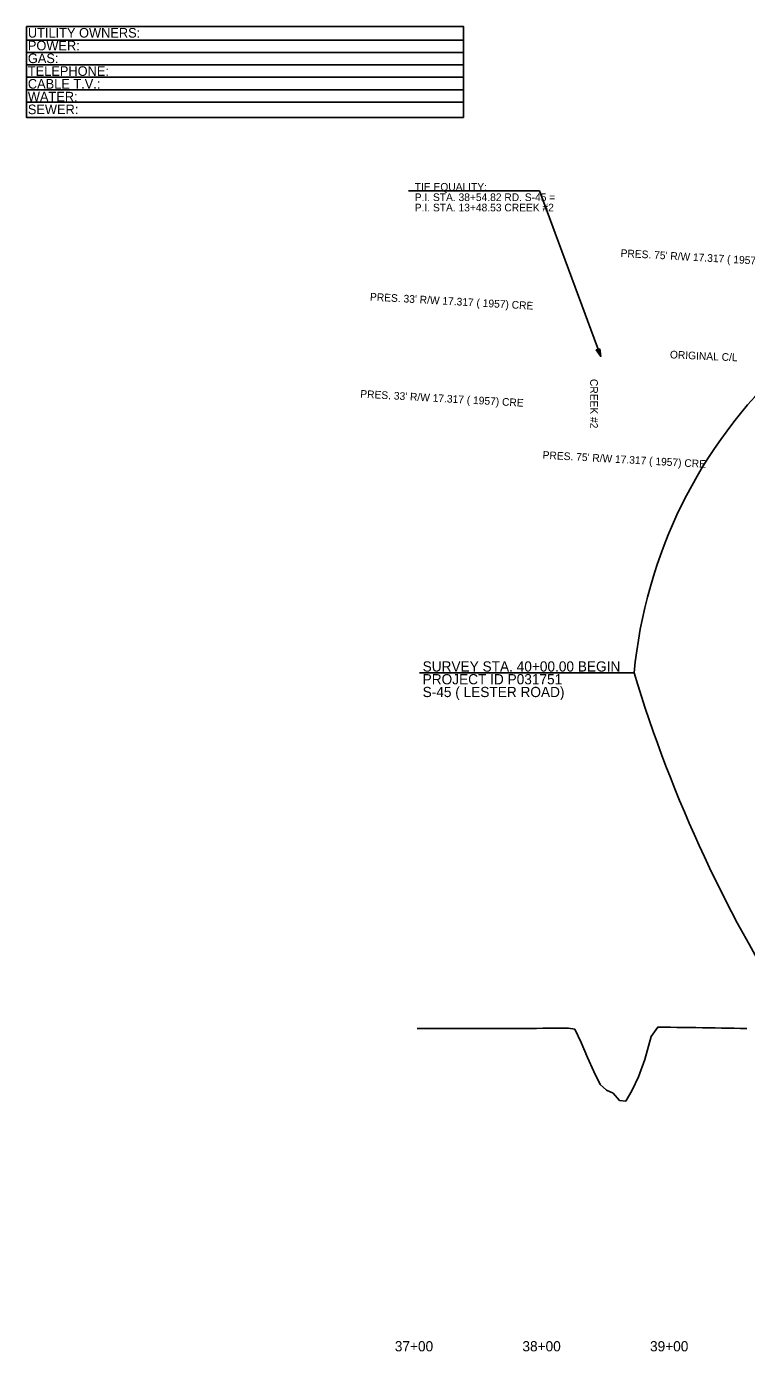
# Model space of a CAD drawing. Extents: x -3336 to 3318, y -3606 to 6276.
# Drawn here: x 119 to 683, y -509 to 529 of the extents above; entities that cross this region are included whole.
import ezdxf

# ---------------------------------------------------------------- set-up
doc = ezdxf.new("R2010")
doc.units = 0
for name, color, linetype in [('RD_DDB_Profile_EX', 7, 'Continuous'), ('RD_DDB_StaTX', 7, 'Continuous'), ('RD_EX_RW_TX', 7, 'Continuous'), ('RD_HC_Data', 7, 'Continuous'), ('RD_PD_Final_TX', 7, 'Continuous'), ('RD_TX_Drainage', 7, 'Continuous'), ('RD_TX_Misc2', 7, 'Continuous'), ('RD_TX_RoadID', 7, 'Continuous')]:
    doc.layers.add(name, color=color, linetype=linetype)

msp = doc.modelspace()

# ---------------------------------------------------------------- linework, layer by layer
at = {"layer": 'RD_DDB_Profile_EX'}
msp.add_lwpolyline([(425, -255.9), (428.4, -255.9), (433.4, -256), (438.4, -256), (443.4, -256), (448.4, -256), (453.4, -256), (458.4, -256), (463.4, -256), (468.4, -256), (473.4, -256), (478.4, -256), (483.4, -255.9), (488.4, -255.9), (493.4, -255.9), (498.4, -255.9), (503.4, -255.9), (508.4, -255.9), (513.4, -255.9), (518.4, -255.9), (523.4, -255.8), (528.4, -255.8), (533.4, -255.8), (538.4, -255.8), (543.4, -255.8), (548.4, -256.6), (553.4, -267), (558.4, -278.7), (563.4, -289.6), (568.4, -299.9), (573.4, -304.4), (578.4, -306.6), (583.4, -312.3), (588.4, -313), (593.4, -304.4), (598.4, -294), (603.4, -280.4), (608.4, -262.3), (613.4, -254.9), (618.4, -254.9), (623.4, -255), (628.4, -255.1), (633.4, -255.2), (638.4, -255.3), (643.4, -255.3), (648.4, -255.4), (653.4, -255.5), (658.4, -255.6), (663.4, -255.7), (668.4, -255.8), (673.4, -255.8), (678.4, -255.9), (683.4, -256)], dxfattribs=at)
at = {"layer": 'RD_HC_Data'}
for p, q in [((520.9, 400.5), (418, 400.5)), ((568.8, 270.6), (520.9, 400.5))]:
    msp.add_line(p, q, dxfattribs=at)
at = {"layer": 'RD_PD_Final_TX'}
msp.add_line((595, 22.7), (426.7, 22.7), dxfattribs=at)
for centre, radius, start, end in [((971.1, -12.8), 377.8, 132.9336, 174.6188), ((1633.5, 337.3), 1085.2, 196.854, 213.1495)]:
    msp.add_arc(centre, radius, start, end, dxfattribs=at)
at = {"layer": 'RD_TX_Drainage'}
msp.add_lwpolyline([(568.1, 276.7), (568.8, 270.6), (565.3, 275.7)], close=True, dxfattribs=at)
at = {"layer": 'RD_TX_Misc2'}
for p, q in [((118.7, 518.6), (461.1, 518.6)), ((118.7, 508.9), (461.1, 508.9)), ((118.7, 499.1), (461.1, 499.1)), ((118.7, 489.4), (461.1, 489.4)), ((118.7, 479.6), (461.1, 479.6)), ((118.7, 469.9), (461.1, 469.9))]:
    msp.add_line(p, q, dxfattribs=at)
msp.add_lwpolyline([(118.7, 529.2), (461.1, 529.2), (461.1, 457.9), (118.7, 457.9)], close=True, dxfattribs=at)

# ---------------------------------------------------------------- texts
at = {"layer": 'RD_DDB_StaTX'}
for s, p in [('37+00', (407.4, -509)), ('38+00', (507.4, -509)), ('39+00', (607.4, -509))]:
    msp.add_text(s, height=8, dxfattribs=at).set_placement(p)
at = {"layer": 'RD_EX_RW_TX'}
for s, p in [("PRES. 75' R/W 17.317 ( 1957) CRE", (584.2, 348.7)), ("PRES. 33' R/W 17.317 ( 1957) CRE", (387.8, 314.5)), ("PRES. 33' R/W 17.317 ( 1957) CRE", (380.2, 238.4)), ("PRES. 75' R/W 17.317 ( 1957) CRE", (523.1, 190.5))]:
    msp.add_text(s, height=6, rotation=356.7861, dxfattribs=at).set_placement(p)
at = {"layer": 'RD_HC_Data'}
for s, p in [('TIE EQUALITY:', (423, 400.5)), ('P.I. STA. 38+54.82 RD. S-45 =', (423, 392.4)), ('P.I. STA. 13+48.53 CREEK #2', (423, 384.3))]:
    msp.add_text(s, height=6, dxfattribs=at).set_placement(p)
at = {"layer": 'RD_PD_Final_TX'}
for s, p in [('SURVEY STA. 40+00.00 BEGIN', (429.2, 23.7)), ('PROJECT ID P031751', (429.2, 13.7)), ('S-45 ( LESTER ROAD)', (429.2, 3.7))]:
    msp.add_text(s, height=8, dxfattribs=at).set_placement(p)
at = {"layer": 'RD_TX_Misc2'}
for s, p in [('UTILITY OWNERS:', (119.8, 520.5)), ('POWER:', (119.8, 510.5)), ('GAS:', (119.8, 500.5)), ('TELEPHONE:', (119.8, 490.5)), ('CABLE T.V.:', (119.8, 480.5)), ('WATER:', (119.8, 470.5)), ('SEWER:', (119.8, 460.5))]:
    msp.add_text(s, height=7.5, dxfattribs=at).set_placement(p)
at = {"layer": 'RD_TX_RoadID'}
for s, rotation, p in [('ORIGINAL C/L', 357.4133, (622.9, 269.2)), ('CREEK #2', 270, (560.5, 253))]:
    msp.add_text(s, height=6, rotation=rotation, dxfattribs=at).set_placement(p)

doc.saveas('drawing.dxf')
